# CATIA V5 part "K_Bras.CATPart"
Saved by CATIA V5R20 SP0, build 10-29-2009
Part number: Bras
Bounding box of the stored display mesh (mm): x -97 to -77, y -116.062 to -56.07, z 96.066 to 116.064
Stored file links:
  G:\Khaled_CFAO_2011\ST2M\ST2M_GR2\plakomicki\Khaled\CAD_ThinkMOTION\K_Bras.CATPart
  G:\Khaled_CFAO_2011\ST2M\ST2M_GR2\plakomicki\Khaled\CAD_ThinkMOTION\K_Jambe.CATProduct
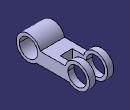
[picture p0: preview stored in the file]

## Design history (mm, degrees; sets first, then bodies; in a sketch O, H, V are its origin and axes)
External parameters (linked from other documents)
  `External.diamètre_liaison_struct_bras` = 15 mm
Set1
  Plane1: linked copy from another document
  Point1: linked copy from another document
  Point2: linked copy from another document
  Plane2: linked copy from another document
Body1 (main body)
  Sketch1 on Plane1, origin (-87, 0, 0), H (0, 1, 0), V (0, 0, 1)
    circle A1 centre (-106.066, 106.066) radius 7.5
    point P1 (-106.066, 106.066)
    circle A2 centre (-66.066, 106.066) radius 7.5
    point P2 (-66.066, 106.066)
    arc A3 centre (-66.066, 106.066) radius 10 from (-72.6804, 98.566) to (-75.7485, 108.566) ccw
    reference projected point E1 (-66.066, 106.066) from Point1
    reference projected point E2 (-106.066, 106.066) from Point2
    axis line L1 (-106.066, 106.066) -> (-66.066, 106.066)
    line L2 (-99.4516, 98.566) -> (-72.6804, 98.566)
    line L3 (-96.3836, 108.566) -> (-75.7485, 108.566)
    arc A4 centre (-106.066, 106.066) radius 10 from (-96.3836, 108.566) to (-99.4516, 98.566) ccw
    radius A1 = 7.5 {= `External.diamètre_liaison_struct_bras` /2}
    radius A2 = 7.5
    radius A3 = 10
    distance L3 L2 = 10
    distance A1 A4 = 2.5
    coincidence: P2 E1, P1 E2
    tangency: L2 A1
    parallelism: L2 L1, L3 L1
  Pad1: profile Sketch1, direction (1, 0, 0), length 10, mirrored extent
  Sketch2 on Plane2, origin (0, -66.066, 0), H (-1, 0, 0), V (0, 0, 1)
    line L1 (82, 121.066) -> (92, 121.066)
    line L2 (92, 121.066) -> (92, 91.066)
    line L3 (92, 91.066) -> (82, 91.066)
    line L4 (82, 91.066) -> (82, 121.066)
    reference intersected line E1 through (87, 0) direction (0, -1) from Plane1
    reference intersected line E2 through (87, 0) direction (0, -1) from Plane1
    reference projected point E3 (87, 106.066) from Point2
    distance E1 L2 = 5
    distance L4 E2 = 5
    distance L3 L1 = 30
    distance L3 E3 = 15
    horizontal: L1 H, L3 H
    vertical: L2 V, L4 V
  Pocket1: profile Sketch2, direction (0, 1, 0), length 19, mirrored extent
